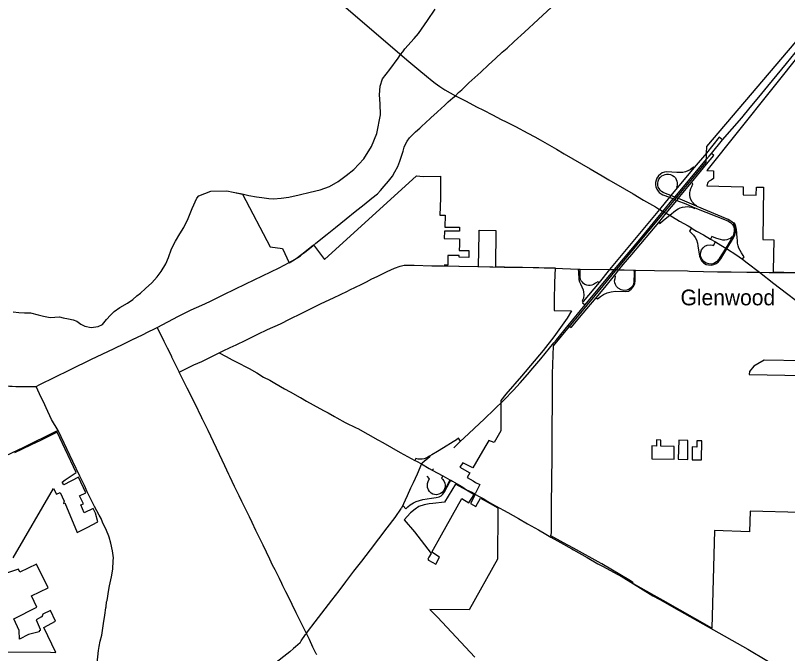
# Model space of a CAD drawing. Extents: x 0 to 851, y 0 to 440.
# Drawn here: x 318.5 to 352.8, y 310.22 to 338.55 of the extents above; entities that cross this region are included whole.
import ezdxf

# ---------------------------------------------------------------- set-up
doc = ezdxf.new("R2010")
doc.units = 0
for name, color, linetype in [('DV_X_Corp_Line', 7, 'Continuous'), ('GM_X_County', 7, 'Continuous'), ('GM_X_Interchange_Ramps', 7, 'Continuous'), ('GM_X_Interstate_Route', 7, 'Continuous'), ('GM_X_State_Route', 7, 'Continuous'), ('GM_X_US_Route', 7, 'Continuous')]:
    doc.layers.add(name, color=color, linetype=linetype)

msp = doc.modelspace()

# ---------------------------------------------------------------- linework, layer by layer
at = {"layer": 'DV_X_Corp_Line'}
for points in [[(353.371, 316.477), (351.135, 316.534), (351.108, 315.619), (349.554, 315.673), (349.439, 311.339), (347.269, 312.572), (346.867, 312.801), (345.96, 313.313), (345.92, 313.368), (345.828, 313.447), (344.545, 314.193), (344.516, 314.209), (343.295, 314.889), (342.853, 315.127), (342.282, 315.439), (342.316, 315.574), (342.317, 316.828), (342.336, 318.957), (342.359, 322.642), (342.408, 323.88), (344.614, 326.548), (345.145, 327.204), (347.297, 329.785), (349.187, 332.038), (349.192, 332.311), (349.193, 332.432), (349.212, 332.74), (353.686, 337.986)], [(353.494, 337.03), (349.218, 331.672), (349.503, 331.658), (349.507, 331.31), (349.402, 331.246), (349.313, 331.19), (349.263, 331.141), (349.214, 330.993), (350.828, 330.946), (350.834, 330.582), (351.405, 330.573), (351.412, 330.934), (351.725, 330.928), (351.704, 328.608), (352.19, 328.596), (352.163, 327.206), (352.164, 327.164), (353.591, 327.124)], [(318.398, 325.396), (318.649, 325.36), (318.897, 325.354), (319.164, 325.344), (319.505, 325.259), (319.746, 325.193), (320.05, 325.139), (320.244, 325.157), (320.452, 325.165), (320.626, 325.129), (320.86, 325.076), (321.06, 325.033), (321.22, 324.974), (321.4, 324.841), (321.576, 324.759), (321.867, 324.692), (322.179, 324.742), (322.364, 324.834), (322.551, 325.054), (322.724, 325.25), (322.88, 325.4), (323.133, 325.588), (323.481, 325.783), (323.72, 325.945), (323.9, 326.098), (324.055, 326.22), (324.285, 326.423), (324.553, 326.675), (324.8, 326.948), (324.967, 327.178), (325.175, 327.519), (325.299, 327.803), (325.434, 328.182), (325.615, 328.533), (325.807, 328.85), (325.974, 329.134), (326.173, 329.538), (326.349, 329.983), (326.552, 330.442), (326.647, 330.541), (327.178, 330.744), (327.89, 330.766), (328.178, 330.7), (328.59, 330.621), (329.821, 328.281), (330.363, 328.204), (330.662, 327.573), (330.814, 327.662), (330.975, 327.765), (331.215, 327.947), (331.74, 328.367), (331.779, 328.315), (332.225, 327.72), (336.314, 331.432), (336.609, 331.406), (337.384, 331.423), (337.375, 330.436), (337.358, 329.687), (337.474, 329.683), (337.583, 329.682), (337.576, 329.148), (338.231, 329.15), (338.229, 328.969), (337.556, 328.979), (337.543, 328.641), (338.224, 328.635), (338.221, 328.368), (338.217, 328.119), (338.645, 328.113), (338.641, 327.804), (338.211, 327.82), (338.212, 327.89), (337.886, 327.889), (337.711, 327.889), (337.703, 327.469), (337.545, 327.469), (337.546, 327.428), (338.211, 327.414), (339.072, 327.405), (339.097, 328.857), (339.1, 329.014), (339.845, 328.997), (339.829, 327.394), (340.225, 327.387), (341.026, 327.375), (342.469, 327.346), (342.453, 326.681), (342.437, 325.91), (342.43, 325.458), (343.208, 325.44), (343.005, 325.117), (342.419, 324.282), (341.939, 323.681), (340.984, 322.531), (340.279, 321.739), (340.058, 321.448), (340.058, 321.218), (340.067, 320.1), (339.77, 319.582), (339.533, 319.676), (339.351, 319.374), (338.978, 318.743), (338.811, 318.46), (338.371, 318.687), (338.248, 318.486), (338.681, 318.237), (338.563, 318.033), (338.829, 317.879), (338.939, 317.814), (339.134, 317.719), (338.933, 317.332), (338.837, 317.297), (338.535, 317.468), (338.05, 317.742), (337.567, 316.94), (337.037, 316.877), (336.883, 316.86), (336.66, 316.814), (336.421, 316.746), (336.25, 316.621), (336.044, 316.461), (335.765, 316.158), (336.227, 315.622), (336.962, 314.655), (336.868, 314.495), (336.817, 314.403), (336.851, 314.356), (337.175, 314.179), (337.342, 314.501), (337, 314.72), (337.423, 315.481), (338.329, 317.102), (338.637, 316.916), (338.875, 317.275), (338.913, 317.254), (338.71, 316.876), (338.955, 316.739), (339.154, 317.117), (339.454, 316.948), (339.581, 316.877), (339.925, 316.681), (339.922, 316.533), (339.913, 314.403), (338.659, 312.156), (336.908, 312.175), (337.242, 311.829), (338.909, 310.055)], [(353.486, 323.221), (351.762, 323.252), (351.481, 323.088), (351.306, 322.981), (351.103, 322.739), (351.088, 322.61), (353.473, 322.569)], [(318.396, 314.465), (320.198, 317.551), (320.326, 317.289), (320.492, 317.367), (320.667, 316.985), (320.632, 316.875), (320.698, 316.908), (321.239, 315.591), (321.686, 315.82), (322.153, 316.065), (322.051, 316.451), (321.952, 316.657), (321.554, 316.465), (321.41, 316.813), (321.517, 316.87), (321.346, 317.222), (321.63, 317.351), (321.298, 318.054), (320.647, 317.714), (320.577, 317.822), (320.711, 317.931), (321.202, 318.254), (320.353, 320.047), (320.059, 319.905), (319.614, 319.681), (319.194, 319.492), (318.793, 319.294), (318.462, 319.131)], [(317.515, 310.294), (320.058, 310.283), (320.289, 310.264), (319.762, 311.37), (320.275, 311.653), (320.056, 312.13), (319.716, 311.965), (319.67, 311.828), (319.654, 311.843), (319.415, 311.71), (319.6, 311.3), (319.599, 311.24), (319.557, 311.229), (319.557, 311.178), (319.074, 311.063), (318.677, 310.853), (318.668, 311.238), (318.431, 311.762), (319.452, 312.281), (319.21, 312.778), (319.954, 313.14), (319.442, 314.19), (318.702, 313.825), (318.637, 313.963), (318.007, 313.758)]]:
    msp.add_lwpolyline(points, dxfattribs=at)
for points in [[(346.764, 319.435), (346.764, 318.867), (347.76, 318.846), (347.767, 319.41), (347.17, 319.425), (347.174, 319.694), (346.976, 319.701), (346.971, 319.43)], [(347.968, 319.686), (347.945, 318.841), (348.365, 318.829), (348.375, 319.674)], [(348.774, 319.665), (348.769, 319.385), (348.565, 319.39), (348.555, 318.825), (348.97, 318.815), (348.99, 319.66)]]:
    msp.add_lwpolyline(points, close=True, dxfattribs=at)
at = {"layer": 'GM_X_County'}
msp.add_lwpolyline([(318.398, 325.396), (318.649, 325.36), (318.897, 325.354), (319.164, 325.344), (319.505, 325.259), (319.746, 325.193), (320.05, 325.139), (320.244, 325.157), (320.452, 325.165), (320.626, 325.129), (320.86, 325.076), (321.06, 325.033), (321.22, 324.974), (321.4, 324.841), (321.576, 324.759), (321.867, 324.692), (322.179, 324.742), (322.364, 324.834), (322.551, 325.054), (322.724, 325.25), (322.88, 325.4), (323.133, 325.588), (323.481, 325.783), (323.72, 325.945), (323.9, 326.098), (324.055, 326.22), (324.285, 326.423), (324.553, 326.675), (324.8, 326.948), (324.967, 327.178), (325.175, 327.519), (325.299, 327.803), (325.434, 328.182), (325.615, 328.533), (325.807, 328.85), (325.974, 329.134), (326.173, 329.538), (326.349, 329.983), (326.552, 330.442), (326.647, 330.541), (327.178, 330.744), (327.89, 330.766), (328.178, 330.7), (328.565, 330.626), (328.873, 330.563), (329.207, 330.496), (329.448, 330.468), (329.749, 330.426), (329.97, 330.412), (330.309, 330.436), (330.642, 330.487), (331.11, 330.586), (331.592, 330.699), (332.03, 330.809), (332.445, 330.956), (332.838, 331.177), (333.185, 331.447), (333.526, 331.71), (333.977, 332.186), (334.323, 332.738), (334.561, 333.313), (334.714, 334.141), (334.706, 334.625), (334.667, 335.026), (334.698, 335.419), (334.801, 335.733), (335.137, 336.151), (335.505, 336.652), (335.607, 336.824), (335.709, 336.938), (335.802, 337.067), (336.216, 337.531), (336.405, 337.746), (336.801, 338.327), (337.139, 338.839)], dxfattribs=at)
at = {"layer": 'GM_X_Interchange_Ramps'}
for points in [[(349.903, 333.03), (349.761, 333.144), (349.197, 332.441), (348.652, 331.806), (347.897, 330.896), (347.613, 330.553), (347.548, 330.478), (347.111, 329.943), (344.895, 327.27), (344.431, 326.695), (343.721, 325.844), (343.683, 325.796), (343.811, 325.698)], [(343.057, 324.787), (343.19, 324.701), (343.721, 325.329), (344.299, 326.018), (344.679, 326.47), (345.11, 327.012), (345.31, 327.263), (345.491, 327.49), (345.876, 327.94), (347.077, 329.366), (347.249, 329.57), (347.411, 329.768), (347.882, 330.343), (347.949, 330.425), (348.006, 330.495), (348.528, 331.133), (349.204, 331.948), (349.523, 332.332), (349.418, 332.43)], [(348.652, 331.806), (348.619, 331.832), (348.558, 331.767), (348.466, 331.704), (348.37, 331.651), (348.263, 331.61), (348.149, 331.584), (348.017, 331.575), (347.882, 331.577), (347.437, 331.608), (347.331, 331.595), (347.233, 331.558), (347.151, 331.509), (347.072, 331.434), (346.995, 331.331), (346.964, 331.242), (346.937, 331.14), (346.937, 331.028), (346.954, 330.939), (346.989, 330.839), (347.044, 330.755), (347.098, 330.698), (347.18, 330.635), (347.26, 330.593), (347.548, 330.478), (347.723, 330.407), (347.882, 330.343), (348.282, 330.183), (348.685, 330.008), (350.149, 329.426), (350.263, 329.36), (350.346, 329.27), (350.392, 329.189), (350.428, 329.083), (350.434, 328.979), (350.418, 328.895), (350.376, 328.773), (350.351, 328.727), (350.291, 328.615), (350.053, 328.222), (349.87, 327.921), (349.748, 327.727), (349.638, 327.605), (349.531, 327.536), (349.414, 327.514), (349.297, 327.519), (349.188, 327.558), (349.084, 327.629), (349.008, 327.714), (348.95, 327.817), (348.931, 327.925), (348.946, 328.041), (348.983, 328.142), (349.043, 328.235), (349.13, 328.31), (349.232, 328.356), (349.355, 328.372), (349.472, 328.358), (349.513, 328.343), (349.603, 328.497)], [(348.527, 329.119), (348.439, 328.969), (348.537, 328.882), (348.622, 328.796), (348.699, 328.69), (348.753, 328.585), (348.791, 328.442), (348.807, 328.322), (348.888, 327.869), (348.925, 327.762), (348.98, 327.66), (349.067, 327.569), (349.18, 327.498), (349.287, 327.472), (349.405, 327.464), (349.529, 327.487), (349.629, 327.532), (349.715, 327.603), (349.775, 327.671), (349.829, 327.749), (349.918, 327.897), (350.098, 328.195), (350.391, 328.68), (350.455, 328.802), (350.491, 328.91), (350.495, 329.006), (350.488, 329.12), (350.459, 329.213), (350.409, 329.313), (350.328, 329.393), (350.241, 329.455), (350.163, 329.492), (348.78, 330.074), (348.756, 330.084), (348.032, 330.394), (347.949, 330.425), (347.788, 330.486), (347.613, 330.553), (347.38, 330.641), (347.275, 330.688), (347.202, 330.735), (347.142, 330.797), (347.094, 330.863), (347.058, 330.935), (347.035, 331.018), (347.033, 331.105), (347.052, 331.188), (347.083, 331.277), (347.139, 331.36), (347.21, 331.425), (347.286, 331.467), (347.358, 331.493), (347.424, 331.508), (347.504, 331.51), (347.604, 331.488), (347.684, 331.452), (347.755, 331.407), (347.815, 331.339), (347.851, 331.273), (347.883, 331.191), (347.895, 331.127), (347.889, 331.032), (347.875, 330.94), (347.867, 330.921), (347.897, 330.896)], [(348.756, 330.084), (348.763, 330.102), (348.661, 330.165), (348.599, 330.227), (348.556, 330.284), (348.506, 330.375), (348.476, 330.468), (348.455, 330.575), (348.465, 330.674), (348.473, 330.769), (348.505, 330.862), (348.541, 330.961), (348.59, 331.082), (348.528, 331.133)], [(347.077, 329.366), (347.136, 329.317), (347.176, 329.356), (347.362, 329.519), (347.562, 329.679), (347.824, 329.888), (347.935, 329.959), (348.035, 330.005), (348.138, 330.041), (348.245, 330.057), (348.346, 330.065), (348.423, 330.057), (348.535, 330.034), (348.676, 329.984), (348.685, 330.008)], [(350.793, 327.724), (350.875, 327.836), (350.83, 327.89), (350.748, 328.005), (350.691, 328.116), (350.638, 328.225), (350.605, 328.325), (350.579, 328.443), (350.568, 328.561), (350.559, 328.685), (350.533, 329.063), (350.508, 329.186), (350.439, 329.339), (350.409, 329.313)], [(350.351, 328.727), (350.339, 328.733), (350.301, 328.692), (350.25, 328.654), (350.18, 328.614), (350.096, 328.586), (350.01, 328.575), (349.93, 328.581), (349.821, 328.6), (349.654, 328.648), (349.464, 328.719), (349.435, 328.731), (349.372, 328.624)], [(343.498, 327.282), (343.514, 327.157), (343.53, 326.828), (343.552, 326.731), (343.6, 326.628), (343.665, 326.504), (343.714, 326.369), (343.741, 326.261), (343.752, 326.142), (343.735, 325.996), (343.681, 325.877), (343.721, 325.844)], [(344.431, 326.695), (344.377, 326.731), (344.273, 326.658), (344.182, 326.606), (344.104, 326.576), (344.027, 326.559), (343.949, 326.557), (343.877, 326.571), (343.796, 326.609), (343.731, 326.65), (343.683, 326.706), (343.635, 326.767), (343.604, 326.832), (343.584, 326.93), (343.59, 327.168), (343.591, 327.281)], [(344.299, 326.018), (344.351, 325.974), (344.491, 326.077), (344.616, 326.158), (344.789, 326.234), (344.956, 326.282), (345.156, 326.304), (345.582, 326.288), (345.734, 326.315), (345.852, 326.396), (345.96, 326.52), (346.014, 326.639), (346.025, 326.779), (346.036, 327.136), (346.037, 327.244)], [(345.974, 327.245), (345.987, 327.125), (345.971, 326.709), (345.939, 326.574), (345.869, 326.477), (345.766, 326.396), (345.653, 326.352), (345.523, 326.342), (345.404, 326.369), (345.275, 326.439), (345.194, 326.52), (345.156, 326.601), (345.123, 326.677), (345.118, 326.774), (345.134, 326.871), (345.155, 326.967), (345.11, 327.012)], [(338.275, 319.646), (338.188, 319.785), (338.088, 319.711), (337.951, 319.614), (337.517, 319.348), (337.246, 319.186), (337.002, 319.044), (336.896, 318.982), (336.772, 318.909), (336.658, 318.866), (336.573, 318.852), (336.47, 318.843), (336.384, 318.855), (336.291, 318.885), (336.239, 318.792)], [(336.896, 318.982), (336.911, 318.955), (336.569, 318.665), (336.541, 318.637)], [(337.484, 318.101), (337.432, 318.007), (337.469, 317.966), (337.532, 317.881), (337.578, 317.785), (337.591, 317.696), (337.588, 317.6), (337.562, 317.526), (337.56, 317.521), (337.517, 317.441), (337.455, 317.369), (337.383, 317.317), (337.301, 317.287), (337.211, 317.268), (337.122, 317.272), (337.038, 317.301), (336.967, 317.344), (336.899, 317.409), (336.842, 317.488), (336.809, 317.583), (336.799, 317.68), (336.808, 317.765), (336.834, 317.859), (336.885, 317.965), (336.893, 317.977), (336.787, 318.093)], [(335.727, 316.77), (335.847, 316.649), (335.927, 316.725), (336.041, 316.819), (336.176, 316.907), (336.294, 316.962), (336.445, 317.015), (336.602, 317.055), (336.797, 317.088), (336.986, 317.111), (337.195, 317.14), (337.32, 317.175), (337.412, 317.225), (337.488, 317.298), (337.559, 317.394), (337.783, 317.808), (337.834, 317.913)], [(337.801, 317.931), (337.749, 317.829), (337.583, 317.519), (337.562, 317.526)]]:
    msp.add_lwpolyline(points, dxfattribs=at)
at = {"layer": 'GM_X_Interstate_Route'}
for points in [[(330.398, 341.309), (335.972, 336.51), (336.419, 336.142), (336.766, 335.854), (337.01, 335.648), (337.15, 335.543), (337.358, 335.397), (337.581, 335.247), (337.809, 335.116), (338.052, 334.985)], [(349.31, 332.298), (349.418, 332.43), (349.903, 333.03), (350.772, 334.013), (351.141, 334.46), (351.524, 334.923), (351.928, 335.41), (352.335, 335.92), (352.752, 336.42), (353.142, 336.9), (353.676, 337.545), (354.098, 338.057), (354.101, 338.062)], [(338.052, 334.985), (338.515, 334.747), (338.985, 334.503), (339.299, 334.341), (339.691, 334.141), (340.083, 333.934), (340.304, 333.823), (340.717, 333.615), (341.264, 333.327), (341.573, 333.159), (341.806, 333.028), (342.116, 332.853), (342.538, 332.613), (342.881, 332.41), (343.259, 332.186), (343.641, 331.967), (344.024, 331.743), (344.557, 331.431), (344.867, 331.256), (345.554, 330.851), (345.937, 330.626), (346.393, 330.358), (346.926, 330.052), (347.111, 329.943), (347.158, 329.915), (347.264, 329.854), (347.411, 329.768), (347.474, 329.731)], [(347.264, 329.854), (347.723, 330.407), (347.788, 330.486), (348.991, 331.924), (349.202, 332.165), (349.31, 332.298)], [(345.109, 327.266), (346.234, 328.61), (347.111, 329.672), (347.264, 329.854)], [(347.474, 329.731), (347.562, 329.679), (347.691, 329.604), (347.996, 329.423), (348.379, 329.204), (348.527, 329.119), (348.603, 329.069), (348.757, 328.98), (349.066, 328.805), (349.372, 328.624), (349.603, 328.497), (349.831, 328.359)], [(349.831, 328.359), (349.978, 328.269), (350.053, 328.222), (350.098, 328.195), (350.128, 328.176), (350.505, 327.931), (350.793, 327.724), (351.001, 327.573), (351.549, 327.147)], [(342.532, 324.155), (343.057, 324.787), (343.811, 325.698), (345.109, 327.266)], [(351.549, 327.147), (351.549, 327.147), (352.188, 326.655), (352.751, 326.221), (353.174, 325.898), (353.383, 325.737), (353.529, 325.618)], [(337.968, 319.347), (338.275, 319.646), (338.419, 319.785), (339.336, 320.637), (340.192, 321.472), (340.619, 321.908), (340.92, 322.239), (341.249, 322.613), (341.489, 322.894), (341.833, 323.305), (342.413, 324.012), (342.532, 324.155)], [(337.016, 318.362), (337.075, 318.424)]]:
    msp.add_lwpolyline(points, dxfattribs=at)
at = {"layer": 'GM_X_State_Route'}
for points in [[(338.052, 334.985), (338.183, 335.125), (338.332, 335.258), (338.533, 335.455), (338.64, 335.562), (339.169, 336.028), (339.517, 336.357), (339.819, 336.635), (340.126, 336.922), (340.341, 337.101), (340.652, 337.402), (341.119, 337.818), (341.718, 338.372), (342.313, 338.917)], [(331.253, 327.961), (331.353, 328.041), (331.71, 328.326), (331.851, 328.438), (332.346, 328.839), (332.718, 329.138), (333.195, 329.519), (333.598, 329.851), (333.99, 330.153), (334.335, 330.437), (334.577, 330.635), (334.714, 330.783), (334.886, 330.976), (335.075, 331.194), (335.251, 331.418), (335.357, 331.604), (335.481, 331.839), (335.581, 332.088), (335.655, 332.299), (335.717, 332.521), (335.775, 332.71), (335.831, 332.842), (335.902, 332.967), (336.01, 333.122), (336.132, 333.252), (336.271, 333.387), (336.457, 333.55), (336.572, 333.656), (336.694, 333.771), (336.955, 334.005), (337.232, 334.259), (337.422, 334.443), (337.557, 334.55), (337.728, 334.715), (337.926, 334.891), (338.052, 334.985)], [(330.654, 327.588), (331.036, 327.788), (331.156, 327.883), (331.253, 327.961)], [(330.217, 327.341), (330.217, 327.341), (330.44, 327.457), (330.654, 327.588)], [(325.74, 325.195), (325.803, 325.228), (326.31, 325.477), (326.777, 325.687), (327.139, 325.851), (327.75, 326.168), (328.735, 326.631), (330.217, 327.341)], [(333.355, 326.37), (333.852, 326.612), (334.088, 326.729), (334.327, 326.852), (334.564, 326.954), (335.013, 327.184), (335.333, 327.331), (335.593, 327.422), (335.767, 327.458), (336.032, 327.457), (336.206, 327.46), (337.002, 327.434), (337.482, 327.428)], [(337.482, 327.428), (338.195, 327.418), (339.042, 327.404)], [(339.042, 327.404), (339.569, 327.392), (339.712, 327.389)], [(339.712, 327.389), (340.215, 327.376), (341.018, 327.371), (342.465, 327.331)], [(342.465, 327.331), (343.498, 327.282), (343.591, 327.281), (344.895, 327.27), (345.109, 327.266)], [(345.109, 327.266), (345.31, 327.263), (345.542, 327.257)], [(345.542, 327.257), (345.974, 327.245), (346.037, 327.244), (346.886, 327.229)], [(346.886, 327.229), (348.352, 327.205), (348.449, 327.202)], [(348.449, 327.202), (349.687, 327.168), (350.292, 327.166), (350.983, 327.155), (351.549, 327.147)], [(351.549, 327.147), (351.981, 327.14), (352.258, 327.136), (352.366, 327.135)], [(352.366, 327.135), (353.06, 327.132), (353.591, 327.124)], [(331.671, 325.552), (332.082, 325.755), (332.628, 326.015), (333.244, 326.316), (333.355, 326.37)], [(331.193, 325.312), (331.571, 325.503), (331.671, 325.552)], [(324.801, 324.695), (325.74, 325.195)], [(330.711, 325.074), (331.193, 325.312)], [(327.557, 323.573), (327.732, 323.661), (328.038, 323.807), (328.304, 323.933), (328.737, 324.14), (329.267, 324.396), (329.7, 324.6), (330.268, 324.856), (330.711, 325.074)], [(326.786, 320.659), (326.779, 320.673), (326.775, 320.681), (326.462, 321.334), (326.127, 322.002), (325.78, 322.705)], [(320.391, 320.124), (320.107, 320.61), (319.867, 321.127), (319.741, 321.388), (319.644, 321.591), (319.414, 322.082)], [(329.175, 315.68), (329.013, 316.034), (328.896, 316.283), (328.664, 316.767), (328.561, 316.975), (328.444, 317.216), (328.237, 317.632), (328.031, 318.073), (327.985, 318.171), (327.809, 318.559), (327.568, 319.059), (327.298, 319.613), (327.058, 320.122), (326.789, 320.655), (326.786, 320.659)], [(317.622, 318.794), (317.676, 318.819), (318.368, 319.149), (318.87, 319.384), (320.312, 320.085)], [(320.312, 320.085), (320.391, 320.124)], [(321.848, 317.077), (321.692, 317.398), (321.562, 317.682), (321.464, 317.88), (321.364, 318.087), (321.045, 318.75), (320.391, 320.124)], [(322.218, 316.363), (322.014, 316.746), (321.876, 317.02), (321.848, 317.077)], [(331.666, 311.435), (331.964, 311.816), (332.258, 312.202), (332.558, 312.59), (332.88, 313.005), (333.184, 313.403), (333.537, 313.868), (333.886, 314.315), (334.27, 314.826), (334.647, 315.317), (335.016, 315.794), (335.369, 316.252), (335.651, 316.677)], [(322.663, 315.39), (322.65, 315.431), (322.549, 315.684), (322.373, 316.055), (322.301, 316.207), (322.218, 316.363)], [(330.334, 313.326), (330.227, 313.546), (330.156, 313.696), (330.032, 313.94), (329.915, 314.147), (329.8, 314.412), (329.502, 315.026), (329.175, 315.68)], [(322.848, 314.34), (322.858, 314.469), (322.808, 314.776), (322.745, 315.123), (322.663, 315.39)], [(322.521, 312.248), (322.527, 312.29), (322.55, 312.511), (322.569, 312.578), (322.645, 313.066), (322.677, 313.216), (322.762, 313.622), (322.822, 313.966), (322.848, 314.34)], [(331.423, 311.11), (331.208, 311.544), (330.964, 312.027), (330.789, 312.397), (330.654, 312.677), (330.505, 312.958), (330.381, 313.229), (330.334, 313.326)], [(322.269, 310.761), (322.331, 311.032), (322.414, 311.554), (322.469, 311.922), (322.521, 312.248)], [(331.471, 311.175), (331.615, 311.369), (331.666, 311.435)], [(331.154, 310.695), (331.198, 310.775), (331.383, 311.056), (331.423, 311.11), (331.471, 311.174), (331.471, 311.175)], [(331.883, 310.167), (331.863, 310.207), (331.716, 310.5), (331.557, 310.836), (331.423, 311.11)], [(322.073, 309.392), (322.114, 309.662), (322.188, 310.35), (322.215, 310.525), (322.269, 310.761)], [(330.853, 310.435), (330.685, 310.298), (330.426, 310.09), (330.214, 309.917), (330.077, 309.814), (329.727, 309.544), (329.489, 309.379), (329.227, 309.207), (328.918, 309.017), (328.599, 308.834), (328.291, 308.671), (327.919, 308.499), (327.51, 308.321), (327.21, 308.211), (326.909, 308.126), (326.66, 308.063), (326.445, 308.009), (326.083, 307.901)], [(331.154, 310.695), (330.948, 310.513), (330.855, 310.437), (330.853, 310.435)]]:
    msp.add_lwpolyline(points, dxfattribs=at)
at = {"layer": 'GM_X_US_Route'}
for points in [[(313.604, 325.357), (315.888, 322.657), (316.165, 322.35), (316.191, 322.327), (316.205, 322.325), (316.248, 322.319), (316.621, 322.266), (317.175, 322.2), (317.559, 322.157), (317.91, 322.118), (318.23, 322.09), (318.353, 322.085), (318.511, 322.079), (318.986, 322.078), (319.414, 322.082)], [(320.915, 322.82), (320.944, 322.834), (321.886, 323.282), (322.862, 323.744), (323.375, 323.995), (323.791, 324.202), (323.8, 324.207), (324.258, 324.43), (324.282, 324.441), (324.801, 324.695)], [(324.801, 324.695), (325.085, 324.082), (325.238, 323.798), (325.427, 323.416), (325.439, 323.393)], [(325.78, 322.705), (326.43, 323.043), (326.777, 323.189), (327.557, 323.573)], [(327.557, 323.573), (327.866, 323.41), (328.134, 323.265), (328.419, 323.115), (328.763, 322.941), (328.876, 322.878)], [(325.439, 323.393), (325.66, 322.945), (325.78, 322.705)], [(319.414, 322.082), (319.578, 322.164), (320.915, 322.82)], [(328.876, 322.878), (329.219, 322.685), (329.52, 322.497), (329.805, 322.35), (330.022, 322.226), (330.454, 321.974), (330.701, 321.841), (331.154, 321.592), (331.166, 321.585)], [(331.166, 321.585), (331.424, 321.429), (331.727, 321.268), (332.187, 321.01), (332.392, 320.899), (332.667, 320.74), (332.772, 320.683)], [(332.772, 320.683), (333.144, 320.48), (333.632, 320.247), (333.711, 320.204)], [(333.711, 320.204), (334.6, 319.713), (334.815, 319.59)], [(334.815, 319.59), (335.597, 319.142), (336.239, 318.792), (336.315, 318.753)], [(336.541, 318.637), (336.341, 318.187), (336.174, 317.799), (336.054, 317.56), (335.907, 317.222), (335.651, 316.677)], [(336.315, 318.753), (336.541, 318.637)], [(336.541, 318.637), (336.88, 318.44)], [(336.88, 318.44), (337.016, 318.362)], [(337.016, 318.362), (337.484, 318.101), (337.801, 317.931), (337.834, 317.913), (337.916, 317.865)], [(337.916, 317.865), (338.328, 317.628)], [(338.328, 317.628), (338.543, 317.491), (338.767, 317.378), (338.846, 317.334)], [(338.846, 317.334), (338.905, 317.3), (339.135, 317.175), (339.305, 317.082), (339.457, 316.987), (339.818, 316.781), (340.38, 316.484), (340.616, 316.342), (340.848, 316.211), (341.249, 315.973), (341.731, 315.709), (342.068, 315.522), (342.28, 315.387)], [(342.28, 315.387), (342.713, 315.145), (343.215, 314.865)], [(343.215, 314.865), (343.296, 314.819), (343.897, 314.479), (344.378, 314.204)], [(344.378, 314.204), (344.456, 314.159), (344.603, 314.08), (344.611, 314.075)], [(344.611, 314.075), (345.232, 313.738)], [(345.232, 313.738), (345.456, 313.616), (345.841, 313.381)], [(345.841, 313.381), (346.816, 312.784), (346.82, 312.782)], [(346.82, 312.782), (347.128, 312.609)], [(347.128, 312.609), (347.744, 312.263)], [(347.744, 312.263), (351.03, 310.415), (352.721, 309.407)]]:
    msp.add_lwpolyline(points, dxfattribs=at)

# ---------------------------------------------------------------- texts
at = {"layer": 'DV_X_Corp_Line'}
msp.add_text('Glenwood', height=0.6979, rotation=0, dxfattribs=at).set_placement((348.045, 325.681))

doc.saveas('drawing.dxf')
